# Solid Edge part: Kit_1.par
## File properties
Sűrűség: 0,000 kg/m^3
Pontosság: 0,990
Author: ahadarics
Last saved by: ahadarics
Revision: 76
Username: ahadarics
Dokumentum tartalom típus: 0
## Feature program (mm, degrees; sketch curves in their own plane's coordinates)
base feature "unnamed BaseFeature 1"
thread "unnamed Thread 1"
chamfer "unnamed Chamfer 1"
sketch for "Furat_1" plane through (0, -45, 8.5) normal (0, 0, 1) x-axis (0, 1, 0)
  hole centre (0, 0) bore radius 2.067
hole "Furat_1" nominal diameter 5 finite  ThreadDepth = 4.5 mm
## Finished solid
Body 1: solid body, 49 faces, 56 edges, 10 vertices.
  Faces by surface: plane 16, cylinder 15, cone 11, torus 7
  Edges by curve: circle 46, line 8, intersection 2
Bounding box of the edges (mm; curved faces can reach further): 19.000 x 28.500 x 18.100, from (-9.5, -67.5, -9.5) to (9.5, -39, 8.6).
Cylindrical faces by radius (mm): R2.067 x2, R3.25 x3, R3.55 x1, R4.5 x1, R4.55 x1, R5.55 x1, R5.6 x1, R6.85 x1, R8 x2, R8.6 x1, R9.5 x1
Conical faces (half-angle, radius in mm at the cone's reference point): 8.8315 deg R4.75 x1, 15 deg R5.55 x1, 20.542 deg R3.55 x1, 24.3997 deg R3.55 x1, 27.3182 deg R3.0335 x1, 29.1112 deg R4.1553 x1, 45 deg R2.317 x1, 45 deg R4.65 x1, 45 deg R4.8 x1, 45 deg R8 x1, 60 deg R7.425 x1
Toroidal faces (ring radius, tube radius in mm): R3.2 r0.2 x1, R3.3 r0.3 x1, R4.3301 r0.2 x1, R4.35 r0.2 x1, R5.35 r0.2 x1, R5.4 r0.2 x2
Planar faces by outward normal: +y 5, +z 2, -y 9
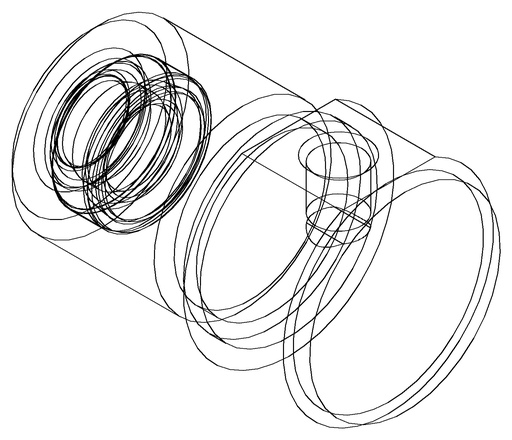
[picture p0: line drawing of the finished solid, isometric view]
